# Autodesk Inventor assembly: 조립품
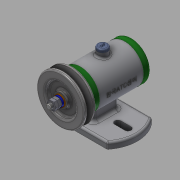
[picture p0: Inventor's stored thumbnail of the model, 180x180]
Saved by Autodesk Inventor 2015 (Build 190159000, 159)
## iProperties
Created: 2017-12
Part Number: 조립품
Document SubType Name: Assembly
Designer: SCD-A03
Author: SCD-A03
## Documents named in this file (14)
- D:\471208V1009\조립품.iam
- D:\471208V1009\V벨트풀리.ipt
- D:\471208V1009\고무캡.ipt
- D:\471208V1009\너트 M 8.ipt
- D:\471208V1009\뒤커버.ipt
- D:\471208V1009\베어링 15 x 32 x 9.ipt
- D:\471208V1009\본체.ipt
- D:\471208V1009\볼트 M4 x 12.ipt
- D:\471208V1009\스프링와셔 8.ipt
- D:\471208V1009\앞커버.ipt
- D:\471208V1009\오일 실 15 25 7.ipt
- D:\471208V1009\와셔 8x17.ipt
- D:\471208V1009\축.ipt
- D:\471208V1009\키 3 x 3 x 12.ipt
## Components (2 placed, 2 different names)
1. V벨트풀리:1 — 각도:2, 플러쉬:1
2. 고무캡:1
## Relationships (2: Angle 1, Flush 1)
- 각도:2 [Angle]: V벨트풀리:1
- 플러쉬:1 [Flush]: V벨트풀리:1
